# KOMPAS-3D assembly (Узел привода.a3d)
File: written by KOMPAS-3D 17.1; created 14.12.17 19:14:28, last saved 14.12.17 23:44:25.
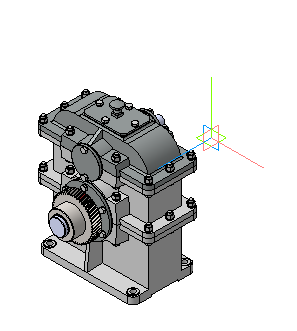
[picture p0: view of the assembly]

Referenced files in C:\Users\Yaroslav\Desktop\ДМ РАсчетка 2\1) 3D Модели\Детали КОМПАС\: Болт (Корпус)_DIN 7990 - M12 x 50-WN.m3d, Щуп.m3d, Гайка (Корпус)_Hexagon Nut ISO 4032 - M12 - W - N.m3d, Болт крышки подшипника_ISO 4015 - M10 x 40 x 26-N.m3d, Болт (Подшипник 1)_ISO 4014 - M12 x 100 x 30-N.m3d, Болт (Подшипник 2)_ISO 4014 - M12 x 120 x 30-N.m3d, Circlips 13942B_gost_Љ®«мж® A55 ѓЋ‘’ 13942-86.m3d, Крышка подшипника 1 (глухая).m3d, Крышка картера.m3d, Болт (Крышки)_ISO 4015 - M10 x 40 x 26-N.m3d, Крышка подшипника 2.m3d, Вал2+Подшипник+Шестерня.a3d, Сапун.m3d, Прокладка верхняя.m3d, Верхняя часть корпуса.m3d, Прокладка крышки подшипника 2.m3d, Пробка.m3d, Прокладка крышки подшипника 1.m3d, Крышка подшипника 1.m3d, Крышка подшипника 2 (глухая).m3d, Прокладка пробки.m3d, Нижняя часть корпуса.m3d, Средняя часть корпуса.m3d, Вал+Подшипнини+Шестерни.a3d
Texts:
  Болт (Корпус)_DIN 7990 - M12 x 50-WN Болт (Корпус)_DIN 7990 - M12 x 50-WN (1)
  Болт (Корпус)_DIN 7990 - M12 x 50-WN
  Болт (Корпус)_DIN 7990 - M12 x 50-WN Болт (Корпус)_DIN 7990 - M12 x 50-WN (2)
  Гайка (Корпус)_Hexagon Nut ISO 4032 - M12 - W - N Гайка (Корпус)_Hexagon Nut ISO 4032 - M12 - W - N (1)
  Гайка (Корпус)_Hexagon Nut ISO 4032 - M12 - W - N
  Гайка (Корпус)_Hexagon Nut ISO 4032 - M12 - W - N Гайка (Корпус)_Hexagon Nut ISO 4032 - M12 - W - N (2)
  Гайка (Корпус)_Hexagon Nut ISO 4032 - M12 - W - N Гайка (Корпус)_Hexagon Nut ISO 4032 - M12 - W - N (3)
  Гайка (Корпус)_Hexagon Nut ISO 4032 - M12 - W - N Гайка (Корпус)_Hexagon Nut ISO 4032 - M12 - W - N (4)
  Болт крышки подшипника_ISO 4015 - M10 x 40 x 26-N Болт крышки подшипника_ISO 4015 - M10 x 40 x 26-N (1)
  Гайка (Корпус)_Hexagon Nut ISO 4032 - M12 - W - N Гайка (Корпус)_Hexagon Nut ISO 4032 - M12 - W - N (5)
  Болт (Подшипник 1)_ISO 4014 - M12 x 100 x 30-N Болт (Подшипник 1)_ISO 4014 - M12 x 100 x 30-N (1)
  Гайка (Корпус)_Hexagon Nut ISO 4032 - M12 - W - N Гайка (Корпус)_Hexagon Nut ISO 4032 - M12 - W - N (6)
  Болт крышки подшипника_ISO 4015 - M10 x 40 x 26-N
  Болт крышки подшипника_ISO 4015 - M10 x 40 x 26-N Болт крышки подшипника_ISO 4015 - M10 x 40 x 26-N (2)
  Болт (Корпус)_DIN 7990 - M12 x 50-WN Болт (Корпус)_DIN 7990 - M12 x 50-WN (3)
  Гайка (Корпус)_Hexagon Nut ISO 4032 - M12 - W - N Гайка (Корпус)_Hexagon Nut ISO 4032 - M12 - W - N (7)
  Болт (Корпус)_DIN 7990 - M12 x 50-WN Болт (Корпус)_DIN 7990 - M12 x 50-WN (4)
  Болт (Корпус)_DIN 7990 - M12 x 50-WN Болт (Корпус)_DIN 7990 - M12 x 50-WN (5)
  Болт (Подшипник 2)_ISO 4014 - M12 x 120 x 30-N Болт (Подшипник 2)_ISO 4014 - M12 x 120 x 30-N (1)
  Circlips 13942B_gost_Љ®«мж® A55 ѓЋ‘’ 13942-86 Circlips 13942B_gost_Љ®«мж® A55 ѓЋ‘’ 13942-86
  Гайка (Корпус)_Hexagon Nut ISO 4032 - M12 - W - N Гайка (Корпус)_Hexagon Nut ISO 4032 - M12 - W - N (8)
  Гайка (Корпус)_Hexagon Nut ISO 4032 - M12 - W - N Гайка (Корпус)_Hexagon Nut ISO 4032 - M12 - W - N (9)
  Гайка (Корпус)_Hexagon Nut ISO 4032 - M12 - W - N Гайка (Корпус)_Hexagon Nut ISO 4032 - M12 - W - N (10)
  Крышка подшипника 1 (глухая) Крышка подшипника 1 (глухая)
  Крышка картера Крышка картера
  Болт крышки подшипника_ISO 4015 - M10 x 40 x 26-N Болт крышки подшипника_ISO 4015 - M10 x 40 x 26-N (3)
  Болт крышки подшипника_ISO 4015 - M10 x 40 x 26-N Болт крышки подшипника_ISO 4015 - M10 x 40 x 26-N (4)
  Болт (Подшипник 2)_ISO 4014 - M12 x 120 x 30-N
  Болт (Подшипник 2)_ISO 4014 - M12 x 120 x 30-N Болт (Подшипник 2)_ISO 4014 - M12 x 120 x 30-N (2)
  Болт (Крышки)_ISO 4015 - M10 x 40 x 26-N Болт (Крышки)_ISO 4015 - M10 x 40 x 26-N (1)
  Крышка подшипника 2 Крышка подшипника 2
  Гайка (Корпус)_Hexagon Nut ISO 4032 - M12 - W - N Гайка (Корпус)_Hexagon Nut ISO 4032 - M12 - W - N (11)
  Болт (Крышки)_ISO 4015 - M10 x 40 x 26-N
  Болт (Крышки)_ISO 4015 - M10 x 40 x 26-N Болт (Крышки)_ISO 4015 - M10 x 40 x 26-N (2)
  Болт крышки подшипника_ISO 4015 - M10 x 40 x 26-N Болт крышки подшипника_ISO 4015 - M10 x 40 x 26-N (5)
  Вал2+Подшипник+Шестерня Вал2+Подшипник+Шестерня
  Болт (Корпус)_DIN 7990 - M12 x 50-WN Болт (Корпус)_DIN 7990 - M12 x 50-WN (6)
  Гайка (Корпус)_Hexagon Nut ISO 4032 - M12 - W - N Гайка (Корпус)_Hexagon Nut ISO 4032 - M12 - W - N (12)
  Гайка (Корпус)_Hexagon Nut ISO 4032 - M12 - W - N Гайка (Корпус)_Hexagon Nut ISO 4032 - M12 - W - N (13)
  Прокладка верхняя Прокладка верхняя
  Болт крышки подшипника_ISO 4015 - M10 x 40 x 26-N Болт крышки подшипника_ISO 4015 - M10 x 40 x 26-N (6)
  Гайка (Корпус)_Hexagon Nut ISO 4032 - M12 - W - N Гайка (Корпус)_Hexagon Nut ISO 4032 - M12 - W - N (14)
  Гайка (Корпус)_Hexagon Nut ISO 4032 - M12 - W - N Гайка (Корпус)_Hexagon Nut ISO 4032 - M12 - W - N (15)
  Болт (Подшипник 2)_ISO 4014 - M12 x 120 x 30-N Болт (Подшипник 2)_ISO 4014 - M12 x 120 x 30-N (3)
  Болт крышки подшипника_ISO 4015 - M10 x 40 x 26-N Болт крышки подшипника_ISO 4015 - M10 x 40 x 26-N (7)
  Болт крышки подшипника_ISO 4015 - M10 x 40 x 26-N Болт крышки подшипника_ISO 4015 - M10 x 40 x 26-N (8)
  Болт крышки подшипника_ISO 4015 - M10 x 40 x 26-N Болт крышки подшипника_ISO 4015 - M10 x 40 x 26-N (9)
  Верхняя часть корпуса Верхняя часть корпуса
  Болт (Корпус)_DIN 7990 - M12 x 50-WN Болт (Корпус)_DIN 7990 - M12 x 50-WN (7)
  Болт (Корпус)_DIN 7990 - M12 x 50-WN Болт (Корпус)_DIN 7990 - M12 x 50-WN (8)
  Прокладка крышки подшипника 2 Прокладка крышки подшипника 2 (1)
  Болт крышки подшипника_ISO 4015 - M10 x 40 x 26-N Болт крышки подшипника_ISO 4015 - M10 x 40 x 26-N (10)
  Болт крышки подшипника_ISO 4015 - M10 x 40 x 26-N Болт крышки подшипника_ISO 4015 - M10 x 40 x 26-N (11)
  Болт (Подшипник 1)_ISO 4014 - M12 x 100 x 30-N
  Болт (Подшипник 1)_ISO 4014 - M12 x 100 x 30-N Болт (Подшипник 1)_ISO 4014 - M12 x 100 x 30-N (2)
  Прокладка крышки подшипника 1 Прокладка крышки подшипника 1 (1)
  Болт крышки подшипника_ISO 4015 - M10 x 40 x 26-N Болт крышки подшипника_ISO 4015 - M10 x 40 x 26-N (12)
  Гайка (Корпус)_Hexagon Nut ISO 4032 - M12 - W - N Гайка (Корпус)_Hexagon Nut ISO 4032 - M12 - W - N (16)
  Гайка (Корпус)_Hexagon Nut ISO 4032 - M12 - W - N Гайка (Корпус)_Hexagon Nut ISO 4032 - M12 - W - N (17)
  Болт (Подшипник 1)_ISO 4014 - M12 x 100 x 30-N Болт (Подшипник 1)_ISO 4014 - M12 x 100 x 30-N (3)
  Болт (Корпус)_DIN 7990 - M12 x 50-WN Болт (Корпус)_DIN 7990 - M12 x 50-WN (9)
  Крышка подшипника 1 Крышка подшипника 1
  Крышка подшипника 2 (глухая) Крышка подшипника 2 (глухая)
  Болт (Крышки)_ISO 4015 - M10 x 40 x 26-N Болт (Крышки)_ISO 4015 - M10 x 40 x 26-N (3)
  Прокладка пробки Прокладка пробки
  Болт (Корпус)_DIN 7990 - M12 x 50-WN Болт (Корпус)_DIN 7990 - M12 x 50-WN (10)
  Болт (Корпус)_DIN 7990 - M12 x 50-WN Болт (Корпус)_DIN 7990 - M12 x 50-WN (11)
  Болт крышки подшипника_ISO 4015 - M10 x 40 x 26-N Болт крышки подшипника_ISO 4015 - M10 x 40 x 26-N (13)
  Прокладка крышки подшипника 1
  Прокладка крышки подшипника 1 Прокладка крышки подшипника 1 (2)
  Болт крышки подшипника_ISO 4015 - M10 x 40 x 26-N Болт крышки подшипника_ISO 4015 - M10 x 40 x 26-N (14)
  Болт крышки подшипника_ISO 4015 - M10 x 40 x 26-N Болт крышки подшипника_ISO 4015 - M10 x 40 x 26-N (15)
  Нижняя часть корпуса Нижняя часть корпуса
  Болт (Корпус)_DIN 7990 - M12 x 50-WN Болт (Корпус)_DIN 7990 - M12 x 50-WN (12)
  Средняя часть корпуса Средняя часть корпуса
  Гайка (Корпус)_Hexagon Nut ISO 4032 - M12 - W - N Гайка (Корпус)_Hexagon Nut ISO 4032 - M12 - W - N (18)
  Болт (Подшипник 1)_ISO 4014 - M12 x 100 x 30-N Болт (Подшипник 1)_ISO 4014 - M12 x 100 x 30-N (4)
  Болт крышки подшипника_ISO 4015 - M10 x 40 x 26-N Болт крышки подшипника_ISO 4015 - M10 x 40 x 26-N (16)
  Гайка (Корпус)_Hexagon Nut ISO 4032 - M12 - W - N Гайка (Корпус)_Hexagon Nut ISO 4032 - M12 - W - N (19)
  Гайка (Корпус)_Hexagon Nut ISO 4032 - M12 - W - N Гайка (Корпус)_Hexagon Nut ISO 4032 - M12 - W - N (20)
  Болт (Подшипник 2)_ISO 4014 - M12 x 120 x 30-N Болт (Подшипник 2)_ISO 4014 - M12 x 120 x 30-N (4)
  Болт (Крышки)_ISO 4015 - M10 x 40 x 26-N Болт (Крышки)_ISO 4015 - M10 x 40 x 26-N (4)
  Прокладка крышки подшипника 2
  Прокладка крышки подшипника 2 Прокладка крышки подшипника 2 (2)
  Точка начала. Х
  Точка начала. Y
  Точка начала. Z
